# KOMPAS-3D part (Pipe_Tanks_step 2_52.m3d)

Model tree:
1. X Axis
2. Y Axis
3. Z Axis  (labels: T-Bend Dn 50; Pipe Dn 50)
     Òîëùèíà ñòåíêè 1 = 1

Referenced files in C:\Documents and Settings\kashirsky\Мои документы\Camtasia Studio\Pipelines3D\Tanks\: Tanks_step 2.a3d
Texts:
  Pipe Dn 50
  Steel ASTM A295
  Three Point Plane
  Plane at Angle
  Line and Point Plane
  Axis through Two Vertices
  Axis of Feature
  Axis of Conical Surface
  Axis through Edge
  Trim by Surface
  Trim by Sketch
  Feature with No History
  Intersection Axis of Two Planes
  Two Line Plane
  Line and Face Plane
  Bend by line
  Hole in sheet body
  Cut in sheet body
  Point in CM
  Linear Dimension from Line to Point
  Surface Finish Symbol
  Geometric Tolerance Symbol
  Leader #1
  Leader #2
  Leader #3
  Shape Deviations and Datum
  Node point number
  Mark of coordination axis
  Node point designation
  Mark/Reference designation with leader
  Mark/reference designation on line
  Mark/Reference designation without leader
  T-Bend Dn 50
  Plane of section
